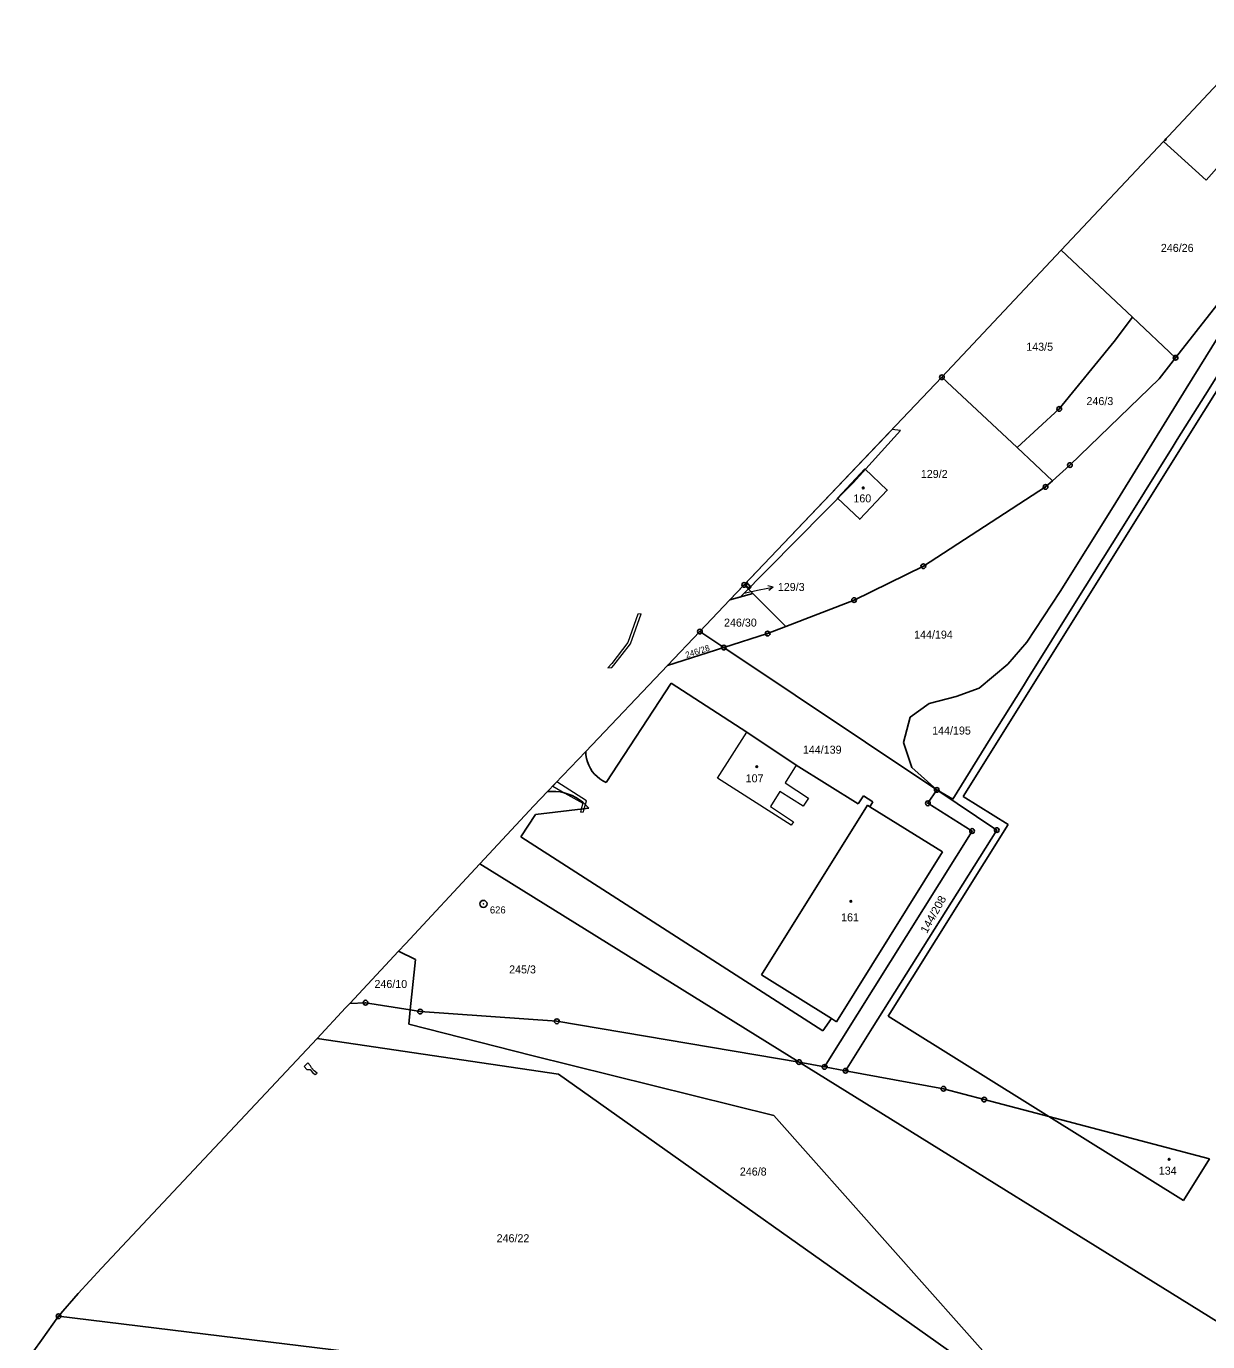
# Model space of a CAD drawing. Extents: x -645290 to -643454, y -1064771 to -1062356.
# Drawn here: x -644569.8 to -644318.9, y -1063369.7 to -1063090.3 of the extents above; entities that cross this region are included whole.
import ezdxf
from ezdxf.enums import TextEntityAlignment as Align

# ---------------------------------------------------------------- set-up
doc = ezdxf.new("R2010")
doc.units = 0
doc.header["$LTSCALE"] = 0.68
for name, color, linetype, lineweight in [('1', 7, 'Continuous', 25), ('13', 7, 'Continuous', 13), ('4', 7, 'Continuous', 13), ('5', 7, 'Continuous', 25), ('7', 7, 'Continuous', 13), ('8', 7, 'Continuous', 25)]:
    doc.layers.add(name, color=color, linetype=linetype, lineweight=lineweight)
doc.layers.add('2', color=7, linetype='Continuous')

msp = doc.modelspace()

# ---------------------------------------------------------------- linework, layer by layer
at = {"layer": '1'}
for p, q in [((-644319.68, -1063172.1), (-644268.56, -1063090.26)), ((-644328.28, -1063114.7), (-644314.55, -1063100.08)), ((-644350, -1063137.84), (-644328.28, -1063114.7)), ((-644319.22, -1063122.92), (-644328.28, -1063114.7)), ((-644315.88, -1063119.2), (-644319.22, -1063122.92)), ((-644375.32, -1063164.82), (-644350, -1063137.84)), ((-644350, -1063137.84), (-644334.87, -1063152.04)), ((-644325.69, -1063160.66), (-644311.7, -1063142.78)), ((-644313.82, -1063151.72), (-644323.44, -1063167.17)), ((-644338.76, -1063157.19), (-644334.87, -1063152.04)), ((-644334.87, -1063152.04), (-644325.69, -1063160.66)), ((-644319.38, -1063168.61), (-644310.27, -1063153.94)), ((-644338.76, -1063157.19), (-644350.39, -1063171.54)), ((-644329.19, -1063165.13), (-644325.69, -1063160.66)), ((-644417.32, -1063208.93), (-644375.32, -1063164.82)), ((-644375.32, -1063164.82), (-644359.33, -1063179.77)), ((-644329.19, -1063165.13), (-644348.13, -1063183.48)), ((-644323.44, -1063167.17), (-644338.97, -1063192.31)), ((-644325.34, -1063178.05), (-644319.38, -1063168.61)), ((-644370.8, -1063253.86), (-644319.68, -1063172.1)), ((-644350.39, -1063171.54), (-644359.33, -1063179.77)), ((-644359.33, -1063179.77), (-644351.86, -1063186.82)), ((-644335.37, -1063194.1), (-644326.22, -1063179.48)), ((-644326.22, -1063179.48), (-644325.34, -1063178.05)), ((-644348.13, -1063183.48), (-644351.86, -1063186.82)), ((-644379.27, -1063204.95), (-644353.3, -1063188.11)), ((-644351.86, -1063186.82), (-644353.3, -1063188.11)), ((-644350.2, -1063210.3), (-644338.97, -1063192.31)), ((-644346.82, -1063212.4), (-644335.37, -1063194.1)), ((-644393.99, -1063212.15), (-644379.27, -1063204.95)), ((-644420.37, -1063212.13), (-644417.32, -1063208.93)), ((-644417.32, -1063208.93), (-644415.5, -1063210.76)), ((-644357.29, -1063221.11), (-644350.2, -1063210.3)), ((-644426.74, -1063218.83), (-644420.37, -1063212.13)), ((-644420.37, -1063212.13), (-644415.5, -1063210.76)), ((-644408.5, -1063217.78), (-644415.5, -1063210.76)), ((-644408.5, -1063217.78), (-644393.99, -1063212.15)), ((-644357.15, -1063228.94), (-644346.82, -1063212.4)), ((-644433.63, -1063226.06), (-644426.74, -1063218.83)), ((-644421.65, -1063222.24), (-644426.74, -1063218.83)), ((-644412.34, -1063219.27), (-644408.5, -1063217.78)), ((-644421.65, -1063222.24), (-644412.34, -1063219.27)), ((-644361.33, -1063225.78), (-644357.29, -1063221.11)), ((-644433.63, -1063226.06), (-644421.65, -1063222.24)), ((-644376.41, -1063252.49), (-644421.65, -1063222.24)), ((-644450.98, -1063244.29), (-644433.63, -1063226.06)), ((-644367.44, -1063230.83), (-644361.33, -1063225.78)), ((-644446.66, -1063250.89), (-644432.84, -1063229.82)), ((-644432.84, -1063229.82), (-644416.78, -1063240.24)), ((-644358.01, -1063230.4), (-644357.15, -1063228.94)), ((-644378.02, -1063234.11), (-644372.29, -1063232.63)), ((-644372.29, -1063232.63), (-644367.44, -1063230.83)), ((-644365.05, -1063241.6), (-644358.01, -1063230.4)), ((-644382.04, -1063237.04), (-644378.02, -1063234.11)), ((-644383.51, -1063242.43), (-644382.04, -1063237.04)), ((-644416.78, -1063240.24), (-644406.29, -1063247.22)), ((-644381.71, -1063247.73), (-644383.51, -1063242.43)), ((-644373.03, -1063254.42), (-644365.05, -1063241.6)), ((-644459.12, -1063252.84), (-644450.98, -1063244.29)), ((-644406.29, -1063247.22), (-644393.12, -1063255.45)), ((-644376.41, -1063252.49), (-644381.71, -1063247.73)), ((-644461.99, -1063255.85), (-644459.12, -1063252.84)), ((-644393.12, -1063255.45), (-644391.97, -1063253.76)), ((-644391.97, -1063253.76), (-644390.03, -1063255.04)), ((-644390.03, -1063255.04), (-644390.61, -1063256.04)), ((-644376.41, -1063252.49), (-644378.31, -1063255.33)), ((-644376.41, -1063252.49), (-644373.03, -1063254.42)), ((-644363.66, -1063261.01), (-644376.41, -1063252.49)), ((-644361.27, -1063259.82), (-644370.8, -1063253.86)), ((-644473.49, -1063268.21), (-644461.99, -1063255.85)), ((-644464.74, -1063262.44), (-644461.67, -1063257.72)), ((-644461.67, -1063257.72), (-644450.32, -1063256.35)), ((-644413.63, -1063291.75), (-644391.12, -1063255.73)), ((-644391.12, -1063255.73), (-644390.61, -1063256.04)), ((-644390.61, -1063256.04), (-644375.18, -1063265.65)), ((-644378.31, -1063255.33), (-644368.91, -1063261.21)), ((-644386.73, -1063300.53), (-644361.27, -1063259.82)), ((-644400.62, -1063303.63), (-644464.74, -1063262.44)), ((-644390.11, -1063303.08), (-644363.66, -1063261.01)), ((-644375.18, -1063265.65), (-644397.72, -1063301.72)), ((-644489.26, -1063285.15), (-644473.49, -1063268.21)), ((-644473.49, -1063268.21), (-644405.68, -1063310.31)), ((-644490.76, -1063286.76), (-644489.26, -1063285.15)), ((-644501.07, -1063297.83), (-644490.76, -1063286.76)), ((-644490.76, -1063286.76), (-644487.12, -1063288.52)), ((-644487.12, -1063288.52), (-644488.24, -1063299.22)), ((-644398.8, -1063301.04), (-644413.63, -1063291.75)), ((-644508.05, -1063305.27), (-644501.98, -1063298.8)), ((-644501.98, -1063298.8), (-644501.07, -1063297.83)), ((-644501.07, -1063297.83), (-644497.75, -1063297.68)), ((-644497.75, -1063297.68), (-644488.24, -1063299.22)), ((-644488.24, -1063299.22), (-644488.56, -1063302.22)), ((-644488.24, -1063299.22), (-644486.15, -1063299.57)), ((-644486.15, -1063299.57), (-644457.12, -1063301.64)), ((-644488.56, -1063302.22), (-644462.42, -1063308.88)), ((-644457.12, -1063301.64), (-644405.68, -1063310.31)), ((-644400.62, -1063303.63), (-644398.8, -1063301.04)), ((-644397.72, -1063301.72), (-644398.8, -1063301.04)), ((-644352.62, -1063321.85), (-644386.73, -1063300.53)), ((-644553.85, -1063354.05), (-644508.05, -1063305.27)), ((-644456.76, -1063312.9), (-644508.05, -1063305.27)), ((-644395.8, -1063312.14), (-644390.11, -1063303.08)), ((-644462.42, -1063308.88), (-644411.05, -1063321.67)), ((-644400.23, -1063311.32), (-644405.68, -1063310.31)), ((-644405.68, -1063310.31), (-644297.96, -1063377.21)), ((-644354.41, -1063385.34), (-644456.76, -1063312.9)), ((-644375, -1063315.97), (-644395.8, -1063312.14)), ((-644366.32, -1063318.25), (-644375, -1063315.97)), ((-644352.62, -1063321.85), (-644366.32, -1063318.25)), ((-644411.05, -1063321.67), (-644354.41, -1063385.34)), ((-644318.46, -1063330.83), (-644352.62, -1063321.85)), ((-644324.02, -1063339.73), (-644352.62, -1063321.85)), ((-644318.46, -1063330.83), (-644324.02, -1063339.73)), ((-644558.81, -1063359.43), (-644553.85, -1063354.05)), ((-644562.97, -1063364.3), (-644558.81, -1063359.43)), ((-644562.97, -1063364.3), (-644452.09, -1063377.81))]:
    msp.add_line(p, q, dxfattribs=at)
msp.add_lwpolyline([(-644391.7, -1063184.29), (-644386.94, -1063188.8), (-644392.78, -1063194.97), (-644397.52, -1063190.51)], close=True, dxfattribs=at)
for points in [[(-644450.98, -1063244.29), (-644450.938, -1063245.047), (-644450.817, -1063245.795), (-644450.619, -1063246.527), (-644450.345, -1063247.234), (-644449.999, -1063247.908), (-644449.583, -1063248.543), (-644449.104, -1063249.13), (-644448.566, -1063249.664), (-644447.975, -1063250.139), (-644447.337, -1063250.549), (-644446.66, -1063250.89)], [(-644459.12, -1063252.84), (-644458.227, -1063252.79), (-644457.332, -1063252.817), (-644456.443, -1063252.923), (-644455.567, -1063253.105), (-644454.71, -1063253.363), (-644453.879, -1063253.695), (-644453.08, -1063254.097), (-644452.319, -1063254.568), (-644451.602, -1063255.103), (-644450.934, -1063255.699), (-644450.32, -1063256.35)], [(-644395.8, -1063312.14), (-644400.23, -1063311.32), (-644368.91, -1063261.21)], [(-644569.81, -1063373.9), (-644566.61, -1063369.36), (-644562.97, -1063364.3)]]:
    msp.add_lwpolyline(points, dxfattribs=at)
at = {"layer": '13'}
for points in [[(-644328.03, -1063114.44), (-644327.88, -1063114.58), (-644327.64, -1063114.32), (-644327.8, -1063114.2)], [(-644385.87, -1063175.9), (-644420.37, -1063212.13), (-644418.15, -1063211.5), (-644394.21, -1063187.22), (-644384.13, -1063176.15)], [(-644416.9, -1063208.49), (-644417.32, -1063208.93), (-644416.58, -1063209.65), (-644416.14, -1063209.23)], [(-644415.81, -1063209.4), (-644416.75, -1063208.33), (-644417.17, -1063208.77), (-644416.24, -1063209.83)], [(-644441.48, -1063221.46), (-644439.22, -1063215.05), (-644439.88, -1063215.12), (-644442.02, -1063221.17), (-644445.45, -1063225.62), (-644446.3, -1063226.55), (-644445.46, -1063226.51), (-644444.99, -1063226.01)], [(-644451.48, -1063257.17), (-644451.29, -1063256.47), (-644451.06, -1063255.58), (-644450.85, -1063254.81), (-644457.15, -1063250.77), (-644458, -1063251.66), (-644455.39, -1063253.15), (-644451.61, -1063255.31), (-644451.93, -1063256.54), (-644452.05, -1063256.99), (-644452.07, -1063257.22)], [(-644509.42, -1063311.11), (-644510, -1063310.48), (-644510.8, -1063311.25), (-644510.22, -1063311.88), (-644509.54, -1063311.88), (-644509, -1063312.51), (-644508.45, -1063312.92), (-644508.01, -1063312.62), (-644508.66, -1063312.15), (-644509.2, -1063311.5)]]:
    msp.add_lwpolyline(points, close=True, dxfattribs=at)
at = {"layer": '4'}
for p, q in [((-644422.96, -1063250.02), (-644416.78, -1063240.24)), ((-644406.29, -1063247.22), (-644408.65, -1063250.98)), ((-644407.32, -1063259.97), (-644422.96, -1063250.02)), ((-644408.65, -1063250.98), (-644403.68, -1063254.23)), ((-644409.72, -1063252.81), (-644411.7, -1063255.98)), ((-644404.77, -1063255.96), (-644409.72, -1063252.81)), ((-644403.68, -1063254.23), (-644404.77, -1063255.96)), ((-644411.7, -1063255.98), (-644406.86, -1063259.24)), ((-644406.86, -1063259.24), (-644407.32, -1063259.97))]:
    msp.add_line(p, q, dxfattribs=at)
at = {"layer": '5'}
for centre in [(-644392.0468, -1063188.3192), (-644414.6468, -1063247.5292), (-644394.6668, -1063276.1492), (-644327.0668, -1063330.9492)]:
    msp.add_circle(centre, 0.175, dxfattribs=at)
at = {"layer": '7'}
msp.add_line((-644411.185, -1063209.386), (-644412.268, -1063209.104), dxfattribs=at)
msp.add_lwpolyline([(-644417.39, -1063210.71), (-644414.12, -1063210.01), (-644411.185, -1063209.386), (-644412.06, -1063210.084)], dxfattribs=at)
at = {"layer": '8'}
for centre, radius in [((-644325.69, -1063160.6599), 0.5), ((-644325.69, -1063160.6599), 0.0303), ((-644375.32, -1063164.8199), 0.5), ((-644375.32, -1063164.8199), 0.0303), ((-644350.39, -1063171.5399), 0.5), ((-644350.39, -1063171.5399), 0.0303), ((-644348.13, -1063183.4799), 0.5), ((-644348.13, -1063183.4799), 0.0303), ((-644353.3, -1063188.1099), 0.5), ((-644353.3, -1063188.1099), 0.0303), ((-644379.27, -1063204.9499), 0.5), ((-644379.27, -1063204.9499), 0.0303), ((-644417.32, -1063208.9299), 0.5), ((-644417.32, -1063208.9299), 0.0303), ((-644393.99, -1063212.1499), 0.5), ((-644393.99, -1063212.1499), 0.0303), ((-644426.74, -1063218.8299), 0.5), ((-644426.74, -1063218.8299), 0.0303), ((-644412.34, -1063219.2699), 0.5), ((-644412.34, -1063219.2699), 0.0303), ((-644421.65, -1063222.2399), 0.5), ((-644421.65, -1063222.2399), 0.0303), ((-644376.41, -1063252.4899), 0.5), ((-644378.31, -1063255.3299), 0.5), ((-644376.41, -1063252.4899), 0.0303), ((-644378.31, -1063255.3299), 0.0303), ((-644368.91, -1063261.2099), 0.5), ((-644363.66, -1063261.0099), 0.5), ((-644368.91, -1063261.2099), 0.0303), ((-644363.66, -1063261.0099), 0.0303), ((-644472.7, -1063276.6898), 0.75), ((-644472.7, -1063276.6898), 0.03), ((-644497.75, -1063297.6799), 0.5), ((-644497.75, -1063297.6799), 0.0303), ((-644486.15, -1063299.5699), 0.5), ((-644486.15, -1063299.5699), 0.0303), ((-644457.12, -1063301.6399), 0.5), ((-644457.12, -1063301.6399), 0.0303), ((-644405.68, -1063310.3099), 0.5), ((-644405.68, -1063310.3099), 0.0303), ((-644400.23, -1063311.3199), 0.5), ((-644400.23, -1063311.3199), 0.0303), ((-644395.8, -1063312.1399), 0.5), ((-644395.8, -1063312.1399), 0.0303), ((-644375, -1063315.9699), 0.5), ((-644375, -1063315.9699), 0.0303), ((-644366.32, -1063318.2499), 0.5), ((-644366.32, -1063318.2499), 0.0303), ((-644562.97, -1063364.2999), 0.5), ((-644562.97, -1063364.2999), 0.0303)]:
    msp.add_circle(centre, radius, dxfattribs=at)

# ---------------------------------------------------------------- texts
at = {"layer": '2'}
for s, p in [('246/26', (-644325.34, -1063138.185)), ('143/5', (-644354.56, -1063159.185)), ('246/3', (-644341.77, -1063170.725)), ('160', (-644392.229, -1063191.395)), ('129/3', (-644407.33, -1063210.225)), ('246/30', (-644418.13, -1063217.785)), ('144/194', (-644377.119, -1063220.334)), ('144/195', (-644373.289, -1063240.715)), ('144/139', (-644400.749, -1063244.785)), ('107', (-644415.109, -1063250.865)), ('161', (-644394.839, -1063280.395)), ('246/10', (-644492.38, -1063294.554)), ('246/8', (-644415.4, -1063334.405)), ('134', (-644327.359, -1063334.215))]:
    msp.add_text(s, height=1.7, dxfattribs=at).set_placement(p, align=Align.CENTER)
for s, p in [('129/2', (-644379.8, -1063186.205)), ('245/3', (-644467.25, -1063291.465)), ('246/22', (-644469.91, -1063348.574))]:
    msp.add_text(s, height=1.7, dxfattribs=at).set_placement(p)
msp.add_text('246/28', height=1.3, rotation=18, dxfattribs=at).set_placement((-644427.0469, -1063223.6657), align=Align.CENTER)
at = {"layer": '2', "width": 1.05}
msp.add_text('144/208', height=1.7, rotation=61, dxfattribs=at).set_placement((-644378.518, -1063283.096))
at = {"layer": '8'}
msp.add_text('626', height=1.5, dxfattribs=at).set_placement((-644471.34, -1063278.725))

doc.saveas('drawing.dxf')
